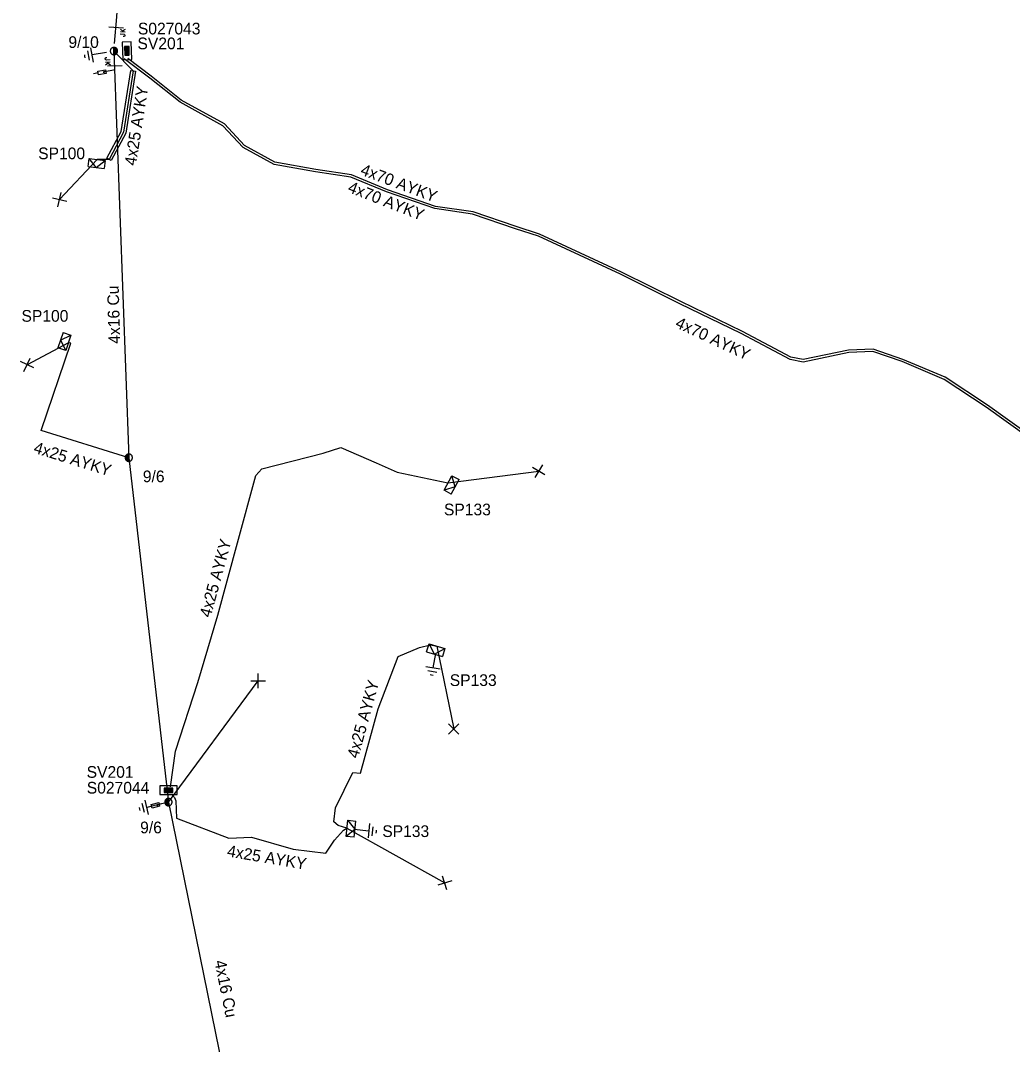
# Model space of a CAD drawing. Extents: x -788458 to -786145, y -1154772 to -1152372.
# Drawn here: x -786961.7 to -786876.9, y -1154691.6 to -1154604 of the extents above; entities that cross this region are included whole.
import ezdxf

# ---------------------------------------------------------------- set-up
doc = ezdxf.new("R2010")
doc.units = 0
for name, color, linetype in [('Vrstva 1', 7, 'Continuous'), ('Vrstva 12', 7, 'Continuous'), ('Vrstva 13', 7, 'Continuous'), ('Vrstva 14', 7, 'Continuous'), ('Vrstva 15', 7, 'Continuous'), ('Vrstva 16', 7, 'Continuous'), ('Vrstva 18', 7, 'Continuous'), ('Vrstva 2', 7, 'Continuous'), ('Vrstva 20', 7, 'Continuous'), ('Vrstva 28', 7, 'Continuous'), ('Vrstva 29', 7, 'Continuous'), ('Vrstva 30', 7, 'Continuous'), ('Vrstva 31', 7, 'Continuous'), ('Vrstva 33', 7, 'Continuous'), ('Vrstva 34', 7, 'Continuous'), ('Vrstva 5', 7, 'Continuous'), ('Vrstva 52', 7, 'Continuous'), ('Vrstva 54', 7, 'Continuous'), ('Vrstva 59', 7, 'Continuous'), ('Vrstva 6', 7, 'Continuous'), ('Vrstva 8', 7, 'Continuous'), ('Vrstva 9', 7, 'Continuous')]:
    doc.layers.add(name, color=color, linetype=linetype)

# ---------------------------------------------------------------- blocks, each defined once
blk = doc.blocks.new('NN440')
at = {"layer": 'Vrstva 2'}
for points in [[(0.63, 0), (0.63, 0.06), (0.62, 0.13), (0.6, 0.19), (0.58, 0.25), (0.55, 0.31), (0.51, 0.37), (0.47, 0.42), (0.42, 0.46), (0.37, 0.51), (0.32, 0.54), (0.26, 0.57), (0.2, 0.59), (0.13, 0.61), (0.07, 0.62), (0, 0.63), (-0.06, 0.62), (-0.13, 0.61), (-0.19, 0.59), (-0.26, 0.57), (-0.31, 0.54), (-0.37, 0.51), (-0.42, 0.46), (-0.47, 0.42), (-0.51, 0.37), (-0.54, 0.31), (-0.57, 0.25), (-0.6, 0.19), (-0.62, 0.13), (-0.63, 0.06), (-0.63, 0), (-0.63, -0.07), (-0.62, -0.14), (-0.6, -0.2), (-0.57, -0.26), (-0.54, -0.32), (-0.51, -0.37), (-0.47, -0.43), (-0.42, -0.47), (-0.37, -0.51), (-0.31, -0.55), (-0.26, -0.58), (-0.19, -0.6), (-0.13, -0.62), (-0.06, -0.63), (0, -0.63), (0.07, -0.63), (0.13, -0.62), (0.2, -0.6), (0.26, -0.58), (0.32, -0.55), (0.37, -0.51), (0.42, -0.47), (0.47, -0.43), (0.51, -0.37), (0.55, -0.32), (0.58, -0.26), (0.6, -0.2), (0.62, -0.14), (0.63, -0.07), (0.63, 0)], [(-0.63, 0), (0.63, 0)], [(-0.6, -0.18), (0.57, -0.18)], [(-0.51, -0.32), (0.5, -0.32)], [(-0.37, -0.47), (0.35, -0.47)]]:
    blk.add_lwpolyline(points, dxfattribs=at)
blk = doc.blocks.new('NN840')
at = {"layer": 'Vrstva 15'}
for points in [[(0.003, 0.619), (0.003, -0.631)], [(-0.745, -0.71), (-0.745, -0.66)], [(-0.73, -0.764), (-0.745, -0.71)], [(-0.657, -0.798), (-0.73, -0.764)], [(-0.627, -0.798), (-0.657, -0.798)], [(-0.558, -0.764), (-0.627, -0.798)], [(-0.538, -0.71), (-0.558, -0.764)], [(-0.538, -0.385), (-0.538, -0.71)], [(-0.332, -0.385), (-0.332, -0.798)], [(-0.332, -0.641), (-0.125, -0.385)], [(-0.263, -0.557), (-0.091, -0.798)]]:
    blk.add_lwpolyline(points, dxfattribs=at)
blk = doc.blocks.new('NN800')
at = {"layer": 'Vrstva 1'}
for points in [[(-0.442, 0.442), (0.442, -0.442)], [(-0.442, -0.442), (0.442, 0.442)]]:
    blk.add_lwpolyline(points, dxfattribs=at)
blk = doc.blocks.new('NN820')
at = {"layer": 'Vrstva 13'}
for points in [[(-0.003, 0.004), (-0.003, -1.049)], [(-0.165, -0.813), (0.165, -0.813)], [(-0.165, -1.473), (-0.165, -0.813)], [(0.165, -0.813), (0.165, -1.473)], [(0.165, -1.473), (-0.165, -1.473)], [(-0.003, -1.049), (-0.062, -0.926)], [(-0.003, -1.049), (0.057, -0.926)], [(-0.003, -1.473), (-0.003, -1.871)]]:
    blk.add_lwpolyline(points, dxfattribs=at)
blk = doc.blocks.new('NN620')
at = {"layer": 'Vrstva 8'}
for points in [[(0.752, 0.004), (-0.748, 0.004)], [(-0.748, 0.004), (-0.748, -0.746)], [(0.752, -0.746), (0.752, 0.004)], [(-0.748, -0.746), (0.752, -0.746)], [(0.368, -0.18), (-0.376, -0.18)], [(-0.376, -0.18), (-0.376, -0.558)], [(-0.376, -0.558), (0.368, -0.558)], [(0.321, -0.227), (-0.329, -0.227)], [(-0.329, -0.227), (-0.329, -0.51)], [(-0.329, -0.51), (0.321, -0.51)], [(0.274, -0.274), (-0.281, -0.274)], [(-0.281, -0.274), (-0.281, -0.463)], [(-0.281, -0.463), (0.274, -0.463)], [(0.227, -0.321), (-0.234, -0.321)], [(-0.234, -0.321), (-0.234, -0.416)], [(-0.234, -0.416), (0.227, -0.416)], [(-0.193, -0.369), (0.185, -0.369)], [(0.227, -0.416), (0.227, -0.321)], [(0.274, -0.463), (0.274, -0.274)], [(0.321, -0.51), (0.321, -0.227)], [(0.368, -0.558), (0.368, -0.18)]]:
    blk.add_lwpolyline(points, dxfattribs=at)
blk = doc.blocks.new('NN630')
at = {"layer": 'Vrstva 9'}
for points in [[(-0.003, -0.7), (-0.703, 0)], [(-0.703, -0.7), (-0.703, 0), (0.697, 0), (0.697, -0.7)], [(-0.703, -0.7), (0.697, -0.7)], [(-0.003, -0.7), (0.697, 0)]]:
    blk.add_lwpolyline(points, dxfattribs=at)
blk = doc.blocks.new('NN810')
at = {"layer": 'Vrstva 14'}
for points in [[(0.004, -0.64), (0.004, -1.89)], [(0.629, -1.89), (-0.621, -1.89)], [(0.388, -2.2), (-0.399, -2.2)], [(0.004, -2.515), (-0.124, -2.515)], [(0.137, -2.515), (0.004, -2.515)]]:
    blk.add_lwpolyline(points, dxfattribs=at)

msp = doc.modelspace()

# ---------------------------------------------------------------- linework, layer by layer
at = {"layer": 'Vrstva 1'}
for points in [[(-786953.694, -1154605.954), (-786953.49, -1154603.668), (-786952.16, -1154584.13), (-786938.55, -1154574.98)], [(-786953.74, -1154606.61), (-786952.47, -1154641.41), (-786949.08, -1154670.89)], [(-786949.08, -1154670.89), (-786942.07, -1154705.39), (-786936.14, -1154733.28), (-786929.32, -1154766.94), (-786928.373, -1154771.804)]]:
    msp.add_lwpolyline(points, dxfattribs=at)
at = {"layer": 'Vrstva 20'}
msp.add_lwpolyline([(-786952.288, -1154608.269), (-786951.892, -1154608.331), (-786952.728, -1154613.625), (-786953.984, -1154615.974), (-786954.336, -1154615.786), (-786953.112, -1154613.495)], close=True, dxfattribs=at)
at = {"layer": 'Vrstva 5'}
for points in [[(-786875.485, -1154639.694), (-786879.127, -1154637.092), (-786882.718, -1154634.708), (-786886.306, -1154633.183), (-786888.804, -1154632.311), (-786890.857, -1154632.419), (-786894.769, -1154633.222), (-786895.894, -1154633.005), (-786900.065, -1154630.779), (-786905.314, -1154628.23), (-786910.403, -1154625.7), (-786917.406, -1154622.453), (-786919.391, -1154621.825), (-786923.064, -1154620.568), (-786926.274, -1154620.098), (-786930.415, -1154618.664), (-786933.477, -1154617.407), (-786936.506, -1154616.949), (-786940.044, -1154616.305), (-786942.692, -1154614.85), (-786944.412, -1154613.01), (-786948.086, -1154610.994), (-786950.681, -1154608.929), (-786952.858, -1154607.277)], [(-786875.375, -1154639.526), (-786879.013, -1154636.928), (-786882.622, -1154634.532), (-786886.234, -1154632.997), (-786888.776, -1154632.109), (-786890.883, -1154632.221), (-786894.771, -1154633.018), (-786895.826, -1154632.815), (-786899.975, -1154630.601), (-786905.226, -1154628.05), (-786910.317, -1154625.52), (-786917.334, -1154622.267), (-786919.329, -1154621.635), (-786923.016, -1154620.372), (-786926.226, -1154619.902), (-786930.345, -1154618.476), (-786933.423, -1154617.213), (-786936.474, -1154616.751), (-786939.976, -1154616.115), (-786942.568, -1154614.69), (-786944.288, -1154612.85), (-786947.974, -1154610.826), (-786950.559, -1154608.771), (-786952.56, -1154607.257)], [(-786948.788, -1154670.24), (-786948.565, -1154670.494), (-786948.44, -1154670.79), (-786948.4, -1154672.26), (-786943.92, -1154673.98), (-786941.98, -1154673.88), (-786938.4, -1154674.93), (-786935.61, -1154675.26), (-786934.86, -1154674.14), (-786934.11, -1154673.28), (-786933.81, -1154673.13)]]:
    msp.add_lwpolyline(points, dxfattribs=at)
at = {"layer": 'Vrstva 52'}
for points in [[(-786953.74, -1154606.61), (-786952.09, -1154608.3), (-786952.92, -1154613.56), (-786954.16, -1154615.88), (-786955.17, -1154615.88)], [(-786952.47, -1154641.41), (-786959.96, -1154639.08), (-786957.42, -1154631.62), (-786957.64, -1154631.58)], [(-786948.898, -1154669.57), (-786948.48, -1154666.53), (-786946.55, -1154660.66), (-786944.84, -1154654.9), (-786943.17, -1154648.69), (-786941.6, -1154642.94), (-786941.08, -1154642.37), (-786935.84, -1154641.01), (-786934.33, -1154640.54), (-786931.295, -1154641.862), (-786929.51, -1154642.64), (-786925.16, -1154643.57)], [(-786933.81, -1154673.13), (-786934.57, -1154672.89), (-786934.94, -1154672.58), (-786934.79, -1154671.39), (-786933.31, -1154668.36), (-786932.65, -1154668.4), (-786931.14, -1154662.9), (-786929.43, -1154658.42), (-786927.59, -1154657.65), (-786926.65, -1154657.44), (-786926.11, -1154657.55)]]:
    msp.add_lwpolyline(points, dxfattribs=at)
at = {"layer": 'Vrstva 59'}
for points in [[(-786955.17, -1154615.88), (-786958.39, -1154619.32)], [(-786957.64, -1154631.58), (-786961.17, -1154633.46)], [(-786925.16, -1154643.57), (-786917.4, -1154642.57)], [(-786926.11, -1154657.55), (-786924.66, -1154664.63)], [(-786949.08, -1154670.89), (-786941.4, -1154660.5)], [(-786933.81, -1154673.13), (-786925.44, -1154677.81)]]:
    msp.add_lwpolyline(points, dxfattribs=at)

# ---------------------------------------------------------------- block references
at = {"layer": 'Vrstva 13'}
for p, xscale, yscale, rotation in [((-786953.74, -1154606.61), 0.5000000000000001, 0.5, 90.17254415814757), ((-786952.47, -1154641.41), 0.5, 0.49999999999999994, -86.33667222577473), ((-786949.08, -1154670.89), 0.5, 0.5, -78.07900824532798)]:
    msp.add_blockref('NN440', p, dxfattribs=dict(at, xscale=xscale, yscale=yscale, rotation=rotation))
at = {"layer": 'Vrstva 15'}
for p, rotation in [((-786953.74, -1154606.61), -79.9191638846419), ((-786926.11, -1154657.55), -10.362550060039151), ((-786949.08, -1154670.89), -76.36437705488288), ((-786933.81, -1154673.13), 83.51696950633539)]:
    msp.add_blockref('NN810', p, dxfattribs=dict(at, rotation=rotation))
at = {"layer": 'Vrstva 16'}
for p, rotation in [((-786953.638, -1154608.229), -80.00395276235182), ((-786949.08, -1154670.89), -75.97179915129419)]:
    msp.add_blockref('NN820', p, dxfattribs=dict(at, rotation=rotation))
at = {"layer": 'Vrstva 18'}
for p, rotation in [((-786953.551, -1154604.58), 86.17492218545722), ((-786953.657, -1154607.886), -87.52477815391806)]:
    msp.add_blockref('NN840', p, dxfattribs=dict(at, rotation=rotation))
at = {"layer": 'Vrstva 28'}
for p, rotation in [((-786952.994, -1154606.599), 92.04540849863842), ((-786949.066, -1154670.24), 180)]:
    msp.add_blockref('NN620', p, dxfattribs=dict(at, rotation=rotation))
at = {"layer": 'Vrstva 31'}
for p, rotation in [((-786955.17, -1154615.88), -7.244613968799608), ((-786957.64, -1154631.58), -108.7186055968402), ((-786925.16, -1154643.57), 61.80327643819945), ((-786926.11, -1154657.55), -16.663479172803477), ((-786933.81, -1154673.13), 84.1093735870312)]:
    msp.add_blockref('NN630', p, dxfattribs=dict(at, rotation=rotation))
at = {"layer": 'Vrstva 34'}
for p, rotation in [((-786958.39, -1154619.32), 32.16885002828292), ((-786961.17, -1154633.46), 109.55200836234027), ((-786917.4, -1154642.57), -165.69022773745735), ((-786941.4, -1154660.5), 45), ((-786924.66, -1154664.63), -90), ((-786925.44, -1154677.81), 152.58107217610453)]:
    msp.add_blockref('NN800', p, dxfattribs=dict(at, rotation=rotation))

# ---------------------------------------------------------------- texts
at = {"layer": 'Vrstva 12'}
for s, p in [('9/10', (-786957.635, -1154606.344)), ('9/6', (-786951.266, -1154643.512)), ('9/6', (-786951.497, -1154673.557))]:
    msp.add_text(s, height=1, dxfattribs=at).set_placement(p)
at = {"layer": 'Vrstva 2'}
for rotation, p in [(91.582, (-786953.197, -1154631.648)), (281.485, (-786945.147, -1154684.516))]:
    msp.add_text('4x16 Cu', height=1, rotation=rotation, dxfattribs=at).set_placement(p)
at = {"layer": 'Vrstva 29'}
for s, p in [('S027043', (-786951.692, -1154605.185)), ('S027044', (-786956.064, -1154670.158))]:
    msp.add_text(s, height=1, dxfattribs=at).set_placement(p)
at = {"layer": 'Vrstva 30'}
for p in [(-786951.728, -1154606.454), (-786956.074, -1154668.808)]:
    msp.add_text('SV201', height=1, dxfattribs=at).set_placement(p)
at = {"layer": 'Vrstva 33'}
for s, p in [('SP100', (-786960.223, -1154615.865)), ('SP100', (-786961.651, -1154629.774)), ('SP133', (-786925.506, -1154646.344)), ('SP133', (-786925.01, -1154660.951)), ('SP133', (-786930.782, -1154673.876))]:
    msp.add_text(s, height=1, dxfattribs=at).set_placement(p)
at = {"layer": 'Vrstva 54'}
for rotation, p in [(81.033, (-786951.863, -1154616.457)), (342.72, (-786960.682, -1154640.97)), (74.803, (-786945.472, -1154655.147)), (74.648, (-786932.849, -1154667.205))]:
    msp.add_text('4x25 AYKY', height=1, rotation=rotation, dxfattribs=at).set_placement(p)
at = {"layer": 'Vrstva 6'}
for s, rotation, p in [('4x70 AYKY', 339.356, (-786932.725, -1154617.157)), ('4x70 AYKY', 338.564, (-786933.808, -1154618.645)), ('4x70 AYKY', 335.086, (-786905.795, -1154630.216)), ('4x25 AYKY', 350.362, (-786944.109, -1154675.533))]:
    msp.add_text(s, height=1, rotation=rotation, dxfattribs=at).set_placement(p)

doc.saveas('drawing.dxf')
